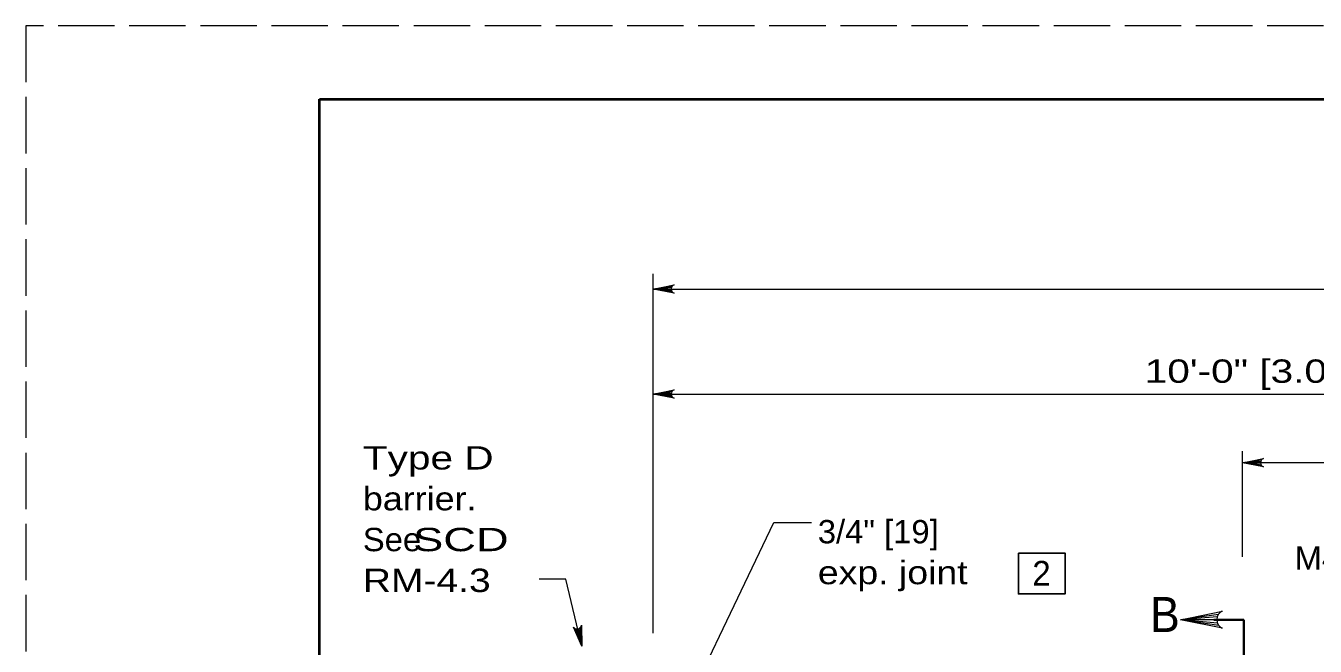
# Model space of a CAD drawing. Extents: x -1431.2 to -1397.2, y -1045.1 to -1001.1.
# Drawn here: x -1431.25 to -1422.47, y -1005.3 to -1001.08 of the extents above; entities that cross this region are included whole.
import ezdxf

# ---------------------------------------------------------------- set-up
doc = ezdxf.new("R2010")
doc.units = 0
doc.header["$LTSCALE"] = 0.064
doc.linetypes.add('LONG_DASHED', pattern=[7.5, 6, -1.5])
doc.layers.add('1', color=7, linetype='Continuous', lineweight=13)

msp = doc.modelspace()

# ---------------------------------------------------------------- linework, layer by layer
at = {"layer": '1', "lineweight": 25}
msp.add_line((-1429.24575, -1001.57983), (-1397.74575, -1001.57983), dxfattribs=at)
at = {"layer": '1'}
for p, q in [((-1426.97675, -1005.2115), (-1426.97675, -1002.76733)), ((-1426.84733, -1002.85225), (-1426.97675, -1002.87033)), ((-1426.85175, -1002.86117), (-1426.97675, -1002.87033)), ((-1426.85308, -1002.87033), (-1426.97675, -1002.87033)), ((-1426.85075, -1002.88192), (-1426.97675, -1002.87033)), ((-1426.84583, -1002.89033), (-1426.97675, -1002.87033)), ((-1426.97675, -1002.87033), (-1410.9895, -1002.87033)), ((-1426.84733, -1003.56667), (-1426.97675, -1003.58475)), ((-1426.85175, -1003.57558), (-1426.97675, -1003.58475)), ((-1426.85308, -1003.58475), (-1426.97675, -1003.58475)), ((-1426.85075, -1003.59642), (-1426.97675, -1003.58475)), ((-1426.84583, -1003.60475), (-1426.97675, -1003.58475)), ((-1426.97675, -1003.58475), (-1410.9895, -1003.58475)), ((-1422.96592, -1004.69267), (-1422.96592, -1003.97283)), ((-1422.83658, -1004.03408), (-1422.96592, -1004.05217)), ((-1422.84092, -1004.04308), (-1422.96592, -1004.05217)), ((-1414.96492, -1004.05217), (-1422.96592, -1004.05217)), ((-1422.84225, -1004.05217), (-1422.96592, -1004.05217)), ((-1422.84, -1004.06383), (-1422.96592, -1004.05217)), ((-1422.835, -1004.07217), (-1422.96592, -1004.05217)), ((-1423.12917, -1005.08358), (-1423.38792, -1005.11975)), ((-1423.138, -1005.1015), (-1423.38792, -1005.11975)), ((-1423.14067, -1005.11975), (-1423.38792, -1005.11975)), ((-1423.13608, -1005.143), (-1423.38792, -1005.11975)), ((-1423.12617, -1005.15975), (-1423.38792, -1005.11975)), ((-1427.50517, -1005.18083), (-1427.46075, -1005.29958)), ((-1427.49583, -1005.18317), (-1427.46075, -1005.29958)), ((-1427.48683, -1005.1825), (-1427.46075, -1005.29958)), ((-1427.47633, -1005.17783), (-1427.46075, -1005.29958)), ((-1427.46942, -1005.17133), (-1427.46075, -1005.29958))]:
    msp.add_line(p, q, dxfattribs=at)
at = {"layer": '1', "lineweight": 35}
for p, q in [((-1423.07017, -1005.11975), (-1423.15958, -1005.11975)), ((-1422.95608, -1005.11975), (-1423.07017, -1005.11975)), ((-1422.95608, -1005.60267), (-1422.95608, -1005.11975))]:
    msp.add_line(p, q, dxfattribs=at)
at = {"layer": '1', "linetype": 'LONG_DASHED'}
msp.add_lwpolyline([(-1431.24575, -1023.07983), (-1397.24575, -1023.07983), (-1397.24575, -1001.07983), (-1431.24575, -1001.07983)], close=True, dxfattribs=at)
at = {"layer": '1', "lineweight": 25}
msp.add_lwpolyline([(-1397.74575, -1022.57983), (-1429.24575, -1022.57983), (-1429.24575, -1001.57983)], dxfattribs=at)
at = {"layer": '1', "lineweight": 40}
msp.add_lwpolyline([(-1429.24575, -1001.57983), (-1397.74575, -1001.57983), (-1397.74575, -1022.57983), (-1429.24575, -1022.57983)], close=True, dxfattribs=at)
at = {"layer": '1'}
for points in [[(-1426.83383, -1002.89892), (-1426.97675, -1002.87033), (-1426.83383, -1002.84175)], [(-1426.83383, -1003.61333), (-1426.97675, -1003.58475), (-1426.83383, -1003.55617)], [(-1422.823, -1004.08075), (-1422.96592, -1004.05217), (-1422.823, -1004.02358)], [(-1426.94142, -1006.10392), (-1426.15542, -1004.45958), (-1425.89817, -1004.45958)], [(-1427.46075, -1005.29958), (-1427.57033, -1004.84383), (-1427.75133, -1004.84383)], [(-1423.10217, -1005.17692), (-1423.38792, -1005.11975), (-1423.10217, -1005.06258)], [(-1427.46392, -1005.15825), (-1427.46075, -1005.29958), (-1427.518, -1005.17033)]]:
    msp.add_lwpolyline(points, dxfattribs=at)
at = {"layer": '1', "lineweight": 25}
msp.add_lwpolyline([(-1424.48975, -1004.66708), (-1424.48975, -1004.94508), (-1424.1725, -1004.94508), (-1424.1725, -1004.66708)], close=True, dxfattribs=at)
at = {"layer": '1'}
for centre, radius in [((-1426.82228, -1002.87028), 0.03084), ((-1426.82229, -1003.58473), 0.03084), ((-1422.81148, -1004.05216), 0.03084), ((-1423.07906, -1005.11969), 0.06168)]:
    msp.add_arc(centre, radius, 112.08782, 247.91395, dxfattribs=at)
msp.add_ellipse((-1427.49338, -1005.15327), major_axis=(0.01201, -0.02742), ratio=0.999895, start_param=4.9044669, end_param=7.27508, dxfattribs=at)

# ---------------------------------------------------------------- texts
for s, height, width, p in [('10\'-0" [3.0 m]', 0.1588, 1.3, (-1423.63033, -1003.50842)), ('Type D', 0.1588, 1.3, (-1428.95183, -1004.09825)), ('barrier.', 0.1588, 1.15, (-1428.95183, -1004.37608)), ('3/4" [19]', 0.1588, 1.05, (-1425.85542, -1004.60067)), ('See', 0.1588, 1.05, (-1428.95183, -1004.654)), ('    SCD', 0.1588, 1.45, (-1428.95183, -1004.65392)), ('M4a', 0.1588, 1.05, (-1422.61033, -1004.78008)), ('exp. joint ', 0.1588, 1.2, (-1425.85542, -1004.8785)), ('RM-4.3', 0.1588, 1.25, (-1428.95183, -1004.93175)), ('B', 0.2382, 0.95, (-1423.59392, -1005.20375))]:
    msp.add_text(s, height=height, dxfattribs=dict(at, width=width)).set_placement(p)
msp.add_text('2', height=0.1682, dxfattribs=at).set_placement((-1424.39558, -1004.88817))

doc.saveas('drawing.dxf')
